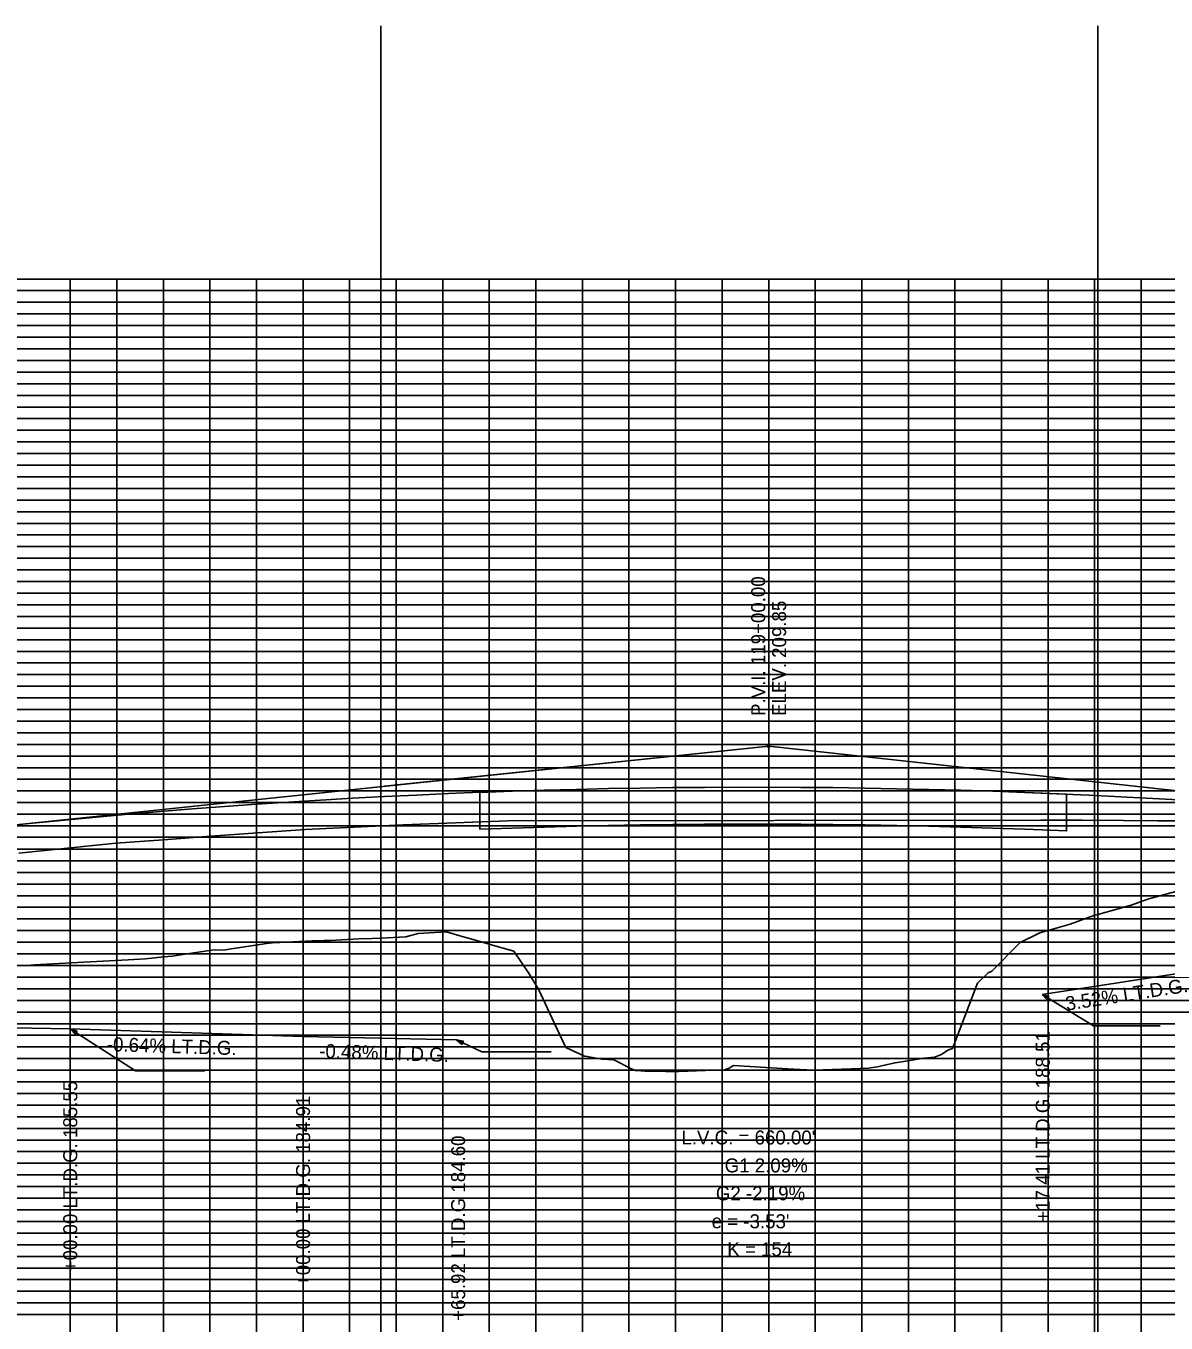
# Model space of a CAD drawing. Extents: x 1451449 to 1456010, y 297581 to 299758.
# Drawn here: x 1453061 to 1453550, y 299105 to 299662 of the extents above; entities that cross this region are included whole.
import ezdxf

# ---------------------------------------------------------------- set-up
doc = ezdxf.new("R2010")
doc.units = 0
for name, color, linetype in [('Existing Profile Grade', 7, 'Continuous'), ('Grid', 7, 'Continuous'), ('Grid_Major', 7, 'Continuous'), ('Grid_Minor', 7, 'Continuous'), ('PR_Exist Surface', 7, 'Continuous'), ('PR_exist_ground', 7, 'Continuous'), ('PR_PGL_point', 7, 'Continuous'), ('PRF_Bridge', 7, 'Continuous'), ('PRF_Scratch', 7, 'Continuous'), ('Profile Annotation', 7, 'Continuous'), ('Profile Annotation Line', 7, 'Continuous'), ('Special_Ditch_LT', 7, 'Continuous')]:
    doc.layers.add(name, color=color, linetype=linetype)

msp = doc.modelspace()

# ---------------------------------------------------------------- linework, layer by layer
at = {"layer": 'Existing Profile Grade'}
msp.add_line((1453496.53, 299321), (1453267.66, 299320.78), dxfattribs=at)
for points in [[(1453057.64, 299306.77), (1453078.47, 299308.95), (1453099.3, 299311.13), (1453119.66, 299312.62), (1453140.01, 299314.12), (1453160.31, 299315.58), (1453180.62, 299317.05), (1453201.65, 299318), (1453222.64, 299318.96), (1453245.15, 299319.87), (1453267.66, 299320.78)], [(1453496.53, 299321), (1453514.29, 299320.93), (1453532.09, 299320.86), (1453546.85, 299320.78), (1453561.6, 299320.71), (1453579.05, 299320.08), (1453596.5, 299319.44), (1453616.07, 299318.37), (1453635.64, 299317.31), (1453650.94, 299316.15)]]:
    msp.add_lwpolyline(points, dxfattribs=at)
at = {"layer": 'Grid'}
for p, q in [((1453213.11, 298828.55), (1453213.11, 299662.3)), ((1453521, 298828.55), (1453521, 299662.3))]:
    msp.add_line(p, q, dxfattribs=at)
at = {"layer": 'Grid_Major'}
for p, q in [((1451479.67, 299553.55), (1455979.67, 299553.55)), ((1451479.67, 299553.55), (1455979.67, 299553.55)), ((1453079.67, 298953.55), (1453079.67, 299553.55)), ((1453179.67, 298953.55), (1453179.67, 299553.55)), ((1453279.67, 298953.55), (1453279.67, 299553.55)), ((1453379.67, 298953.55), (1453379.67, 299553.55)), ((1453479.67, 298953.55), (1453479.67, 299553.55)), ((1451479.67, 299503.55), (1455979.67, 299503.55)), ((1451479.67, 299453.55), (1455979.67, 299453.55)), ((1451479.67, 299403.55), (1455979.67, 299403.55)), ((1451479.67, 299353.55), (1455979.67, 299353.55)), ((1451479.67, 299303.55), (1455979.67, 299303.55)), ((1451479.67, 299253.55), (1455979.67, 299253.55)), ((1451479.67, 299203.55), (1455979.67, 299203.55)), ((1451479.67, 299153.55), (1455979.67, 299153.55))]:
    msp.add_line(p, q, dxfattribs=at)
at = {"layer": 'Grid_Minor'}
for p, q in [((1453099.67, 298953.55), (1453099.67, 299553.55)), ((1453119.67, 298953.55), (1453119.67, 299553.55)), ((1453139.67, 298953.55), (1453139.67, 299553.55)), ((1453159.67, 298953.55), (1453159.67, 299553.55)), ((1453199.67, 298953.55), (1453199.67, 299553.55)), ((1453219.67, 298953.55), (1453219.67, 299553.55)), ((1453239.67, 298953.55), (1453239.67, 299553.55)), ((1453259.67, 298953.55), (1453259.67, 299553.55)), ((1453299.67, 298953.55), (1453299.67, 299553.55)), ((1453319.67, 298953.55), (1453319.67, 299553.55)), ((1453339.67, 298953.55), (1453339.67, 299553.55)), ((1453359.67, 298953.55), (1453359.67, 299553.55)), ((1453399.67, 298953.55), (1453399.67, 299553.55)), ((1453419.67, 298953.55), (1453419.67, 299553.55)), ((1453439.67, 298953.55), (1453439.67, 299553.55)), ((1453459.67, 298953.55), (1453459.67, 299553.55)), ((1453499.67, 298953.55), (1453499.67, 299553.55)), ((1453519.67, 298953.55), (1453519.67, 299553.55)), ((1453539.67, 298953.55), (1453539.67, 299553.55)), ((1451479.67, 299548.55), (1455979.67, 299548.55)), ((1451479.67, 299543.55), (1455979.67, 299543.55)), ((1451479.67, 299538.55), (1455979.67, 299538.55)), ((1451479.67, 299533.55), (1455979.67, 299533.55)), ((1451479.67, 299528.55), (1455979.67, 299528.55)), ((1451479.67, 299523.55), (1455979.67, 299523.55)), ((1451479.67, 299518.55), (1455979.67, 299518.55)), ((1451479.67, 299513.55), (1455979.67, 299513.55)), ((1451479.67, 299508.55), (1455979.67, 299508.55)), ((1451479.67, 299498.55), (1455979.67, 299498.55)), ((1451479.67, 299493.55), (1455979.67, 299493.55)), ((1451479.67, 299488.55), (1455979.67, 299488.55)), ((1451479.67, 299483.55), (1455979.67, 299483.55)), ((1451479.67, 299478.55), (1455979.67, 299478.55)), ((1451479.67, 299473.55), (1455979.67, 299473.55)), ((1451479.67, 299468.55), (1455979.67, 299468.55)), ((1451479.67, 299463.55), (1455979.67, 299463.55)), ((1451479.67, 299458.55), (1455979.67, 299458.55)), ((1451479.67, 299448.55), (1455979.67, 299448.55)), ((1451479.67, 299443.55), (1455979.67, 299443.55)), ((1451479.67, 299438.55), (1455979.67, 299438.55)), ((1451479.67, 299433.55), (1455979.67, 299433.55)), ((1451479.67, 299428.55), (1455979.67, 299428.55)), ((1451479.67, 299423.55), (1455979.67, 299423.55)), ((1451479.67, 299418.55), (1455979.67, 299418.55)), ((1451479.67, 299413.55), (1455979.67, 299413.55)), ((1451479.67, 299408.55), (1455979.67, 299408.55)), ((1451479.67, 299398.55), (1455979.67, 299398.55)), ((1451479.67, 299393.55), (1455979.67, 299393.55)), ((1451479.67, 299388.55), (1455979.67, 299388.55)), ((1451479.67, 299383.55), (1455979.67, 299383.55)), ((1451479.67, 299378.55), (1455979.67, 299378.55)), ((1451479.67, 299373.55), (1455979.67, 299373.55)), ((1451479.67, 299368.55), (1455979.67, 299368.55)), ((1451479.67, 299363.55), (1455979.67, 299363.55)), ((1451479.67, 299358.55), (1455979.67, 299358.55)), ((1451479.67, 299348.55), (1455979.67, 299348.55)), ((1451479.67, 299343.55), (1455979.67, 299343.55)), ((1451479.67, 299338.55), (1455979.67, 299338.55)), ((1451479.67, 299333.55), (1455979.67, 299333.55)), ((1451479.67, 299328.55), (1455979.67, 299328.55)), ((1451479.67, 299323.55), (1455979.67, 299323.55)), ((1451479.67, 299318.55), (1455979.67, 299318.55)), ((1451482.2, 299313.64), (1455982.2, 299313.64)), ((1451479.67, 299308.55), (1455979.67, 299308.55)), ((1451479.67, 299298.55), (1455979.67, 299298.55)), ((1451479.67, 299293.55), (1455979.67, 299293.55)), ((1451479.67, 299288.55), (1455979.67, 299288.55)), ((1451479.67, 299283.55), (1455979.67, 299283.55)), ((1451479.67, 299278.55), (1455979.67, 299278.55)), ((1451479.67, 299273.55), (1455979.67, 299273.55)), ((1451479.67, 299268.55), (1455979.67, 299268.55)), ((1451479.67, 299263.55), (1455979.67, 299263.55)), ((1451479.67, 299258.55), (1455979.67, 299258.55)), ((1451479.67, 299248.55), (1455979.67, 299248.55)), ((1451479.67, 299243.55), (1455979.67, 299243.55)), ((1451479.67, 299238.55), (1455979.67, 299238.55)), ((1451479.67, 299233.55), (1455979.67, 299233.55)), ((1451479.67, 299228.55), (1455979.67, 299228.55)), ((1451479.67, 299223.55), (1455979.67, 299223.55)), ((1451479.67, 299218.55), (1455979.67, 299218.55)), ((1451479.67, 299213.55), (1455979.67, 299213.55)), ((1451479.67, 299208.55), (1455979.67, 299208.55)), ((1451479.67, 299198.55), (1455979.67, 299198.55)), ((1451479.67, 299193.55), (1455979.67, 299193.55)), ((1451479.67, 299188.55), (1455979.67, 299188.55)), ((1451479.67, 299183.55), (1455979.67, 299183.55)), ((1451479.67, 299178.55), (1455979.67, 299178.55)), ((1451479.67, 299173.55), (1455979.67, 299173.55)), ((1451479.67, 299168.55), (1455979.67, 299168.55)), ((1451479.67, 299163.55), (1455979.67, 299163.55)), ((1451479.67, 299158.55), (1455979.67, 299158.55)), ((1451479.67, 299148.55), (1455979.67, 299148.55)), ((1451479.67, 299143.55), (1455979.67, 299143.55)), ((1451479.67, 299138.55), (1455979.67, 299138.55)), ((1451479.67, 299133.55), (1455979.67, 299133.55)), ((1451479.67, 299128.55), (1455979.67, 299128.55)), ((1451479.67, 299123.55), (1455979.67, 299123.55)), ((1451479.67, 299118.55), (1455979.67, 299118.55)), ((1451479.67, 299113.55), (1455979.67, 299113.55)), ((1451479.67, 299108.55), (1455979.67, 299108.55))]:
    msp.add_line(p, q, dxfattribs=at)
at = {"layer": 'PR_Exist Surface'}
msp.add_lwpolyline([(1453060, 299258.49), (1453061.09, 299258.58), (1453064.38, 299258.88), (1453082.8, 299259.84), (1453104.52, 299261.04), (1453111.93, 299261.48), (1453115.98, 299261.86), (1453119.88, 299262.23), (1453123.62, 299262.59), (1453126.24, 299262.98), (1453141.39, 299265.29), (1453145.64, 299265.19), (1453147.96, 299265.54), (1453164, 299267.99), (1453167.89, 299268.38), (1453169.68, 299268.46), (1453183.6, 299269.1), (1453188.57, 299269.24), (1453191.4, 299269.36), (1453203.62, 299269.95), (1453209.36, 299270.13), (1453213.11, 299270.31), (1453223.79, 299270.83), (1453229.11, 299272.26), (1453241.27, 299272.97), (1453247.01, 299271.25), (1453255.73, 299268.84), (1453261.07, 299267.24), (1453270.22, 299264.73), (1453276.82, 299255.02), (1453280.97, 299248.15), (1453287.6, 299233.92), (1453292.52, 299223.38), (1453300.5, 299219.59), (1453301.75, 299219.49), (1453308, 299218.34), (1453313.2, 299217.99), (1453321.06, 299214.02), (1453321.46, 299213.85), (1453322.04, 299213.56), (1453322.83, 299213.33), (1453322.86, 299213.42), (1453326.6, 299213.14), (1453335.46, 299213.01), (1453341.09, 299212.96), (1453352.57, 299213.38), (1453360.67, 299213.65), (1453362.68, 299214.47), (1453364.53, 299215.63), (1453387.77, 299214.17), (1453398.72, 299213.53), (1453415.28, 299214.2), (1453422.66, 299214.44), (1453424.35, 299214.71), (1453426.39, 299215.04), (1453427.59, 299215.3), (1453429.48, 299215.71), (1453433.96, 299216.73), (1453437.71, 299217.35), (1453444.57, 299218.43), (1453446.34, 299218.77), (1453450.92, 299219.13), (1453453.87, 299220.36), (1453456.16, 299221.84), (1453457.32, 299222.45), (1453458.61, 299222.85), (1453460.06, 299226.66), (1453469.36, 299250.95), (1453474.02, 299255.39), (1453475.58, 299256.08), (1453487.67, 299268.37), (1453496.2, 299272.53), (1453509.12, 299276.3), (1453519.36, 299279.99), (1453521, 299280.45), (1453535.38, 299284.5), (1453542.5, 299287.03), (1453543.02, 299287.17), (1453562.38, 299292.43)], dxfattribs=at)
at = {"layer": 'PR_exist_ground'}
for p, q in [((1453522.25, 299232.68), (1453547.81, 299232.68)), ((1453259.47, 299221.42), (1453286.24, 299221.42)), ((1453110.73, 299213.35), (1453137.48, 299213.35))]:
    msp.add_line(p, q, dxfattribs=at)
for points in [[(1453049.67, 299318.31), (1453063.42, 299319.72), (1453077.17, 299321.06), (1453090.92, 299322.34), (1453104.67, 299323.57), (1453118.42, 299324.73), (1453132.17, 299325.83), (1453145.92, 299326.87), (1453159.67, 299327.84), (1453173.42, 299328.76), (1453187.17, 299329.62), (1453200.92, 299330.41), (1453214.67, 299331.14), (1453228.42, 299331.81), (1453242.17, 299332.42), (1453255.92, 299332.97), (1453269.67, 299333.46), (1453283.42, 299333.89), (1453297.17, 299334.25), (1453310.92, 299334.55), (1453324.67, 299334.8), (1453338.42, 299334.98), (1453352.17, 299335.1), (1453365.92, 299335.16), (1453393.42, 299335.09), (1453407.17, 299334.97), (1453420.92, 299334.78), (1453434.67, 299334.53), (1453448.42, 299334.22), (1453462.17, 299333.85), (1453475.92, 299333.42), (1453489.67, 299332.93), (1453503.42, 299332.38), (1453517.17, 299331.76), (1453530.92, 299331.08), (1453544.67, 299330.35), (1453558.42, 299329.55)], [(1453049.67, 299318.31), (1453063.42, 299319.72), (1453077.17, 299321.06), (1453090.92, 299322.34), (1453104.67, 299323.57), (1453118.42, 299324.73), (1453132.17, 299325.83), (1453145.92, 299326.87), (1453159.67, 299327.84), (1453173.42, 299328.76), (1453187.17, 299329.62), (1453200.92, 299330.41), (1453214.67, 299331.14), (1453228.42, 299331.81), (1453242.17, 299332.42), (1453255.92, 299332.97), (1453269.67, 299333.46), (1453283.42, 299333.89), (1453297.17, 299334.25), (1453310.92, 299334.55), (1453324.67, 299334.8), (1453338.42, 299334.98), (1453352.17, 299335.1), (1453365.92, 299335.16), (1453393.42, 299335.09), (1453407.17, 299334.97), (1453420.92, 299334.78), (1453434.67, 299334.53), (1453448.42, 299334.22), (1453462.17, 299333.85), (1453475.92, 299333.42), (1453489.67, 299332.93), (1453503.42, 299332.38), (1453517.17, 299331.76), (1453530.92, 299331.08), (1453544.67, 299330.35), (1453558.42, 299329.55)], [(1453049.67, 299318.31), (1453063.42, 299319.72), (1453077.17, 299321.06), (1453090.92, 299322.34), (1453104.67, 299323.57), (1453118.42, 299324.73), (1453132.17, 299325.83), (1453145.92, 299326.87), (1453159.67, 299327.84), (1453173.42, 299328.76), (1453187.17, 299329.62), (1453200.92, 299330.41), (1453214.67, 299331.14), (1453228.42, 299331.81), (1453242.17, 299332.42), (1453255.92, 299332.97), (1453269.67, 299333.46), (1453283.42, 299333.89), (1453297.17, 299334.25), (1453310.92, 299334.55), (1453324.67, 299334.8), (1453338.42, 299334.98), (1453352.17, 299335.1), (1453365.92, 299335.16), (1453393.42, 299335.09), (1453407.17, 299334.97), (1453420.92, 299334.78), (1453434.67, 299334.53), (1453448.42, 299334.22), (1453462.17, 299333.85), (1453475.92, 299333.42), (1453489.67, 299332.93), (1453503.42, 299332.38), (1453517.17, 299331.76), (1453530.92, 299331.08), (1453544.67, 299330.35), (1453558.42, 299329.55)], [(1453049.67, 299318.31), (1453063.42, 299319.72), (1453077.17, 299321.06), (1453090.92, 299322.34), (1453104.67, 299323.57), (1453118.42, 299324.73), (1453132.17, 299325.83), (1453145.92, 299326.87), (1453159.67, 299327.84), (1453173.42, 299328.76), (1453187.17, 299329.62), (1453200.92, 299330.41), (1453214.67, 299331.14), (1453228.42, 299331.81), (1453242.17, 299332.42), (1453255.92, 299332.97), (1453269.67, 299333.46), (1453283.42, 299333.89), (1453297.17, 299334.25), (1453310.92, 299334.55), (1453324.67, 299334.8), (1453338.42, 299334.98), (1453352.17, 299335.1), (1453365.92, 299335.16), (1453393.42, 299335.09), (1453407.17, 299334.97), (1453420.92, 299334.78), (1453434.67, 299334.53), (1453448.42, 299334.22), (1453462.17, 299333.85), (1453475.92, 299333.42), (1453489.67, 299332.93), (1453503.42, 299332.38), (1453517.17, 299331.76), (1453530.92, 299331.08), (1453544.67, 299330.35), (1453558.42, 299329.55)], [(1453049.67, 299318.31), (1453063.42, 299319.72), (1453077.17, 299321.06), (1453090.92, 299322.34), (1453104.67, 299323.57), (1453118.42, 299324.73), (1453132.17, 299325.83), (1453145.92, 299326.87), (1453159.67, 299327.84), (1453173.42, 299328.76), (1453187.17, 299329.62), (1453200.92, 299330.41), (1453214.67, 299331.14), (1453228.42, 299331.81), (1453242.17, 299332.42), (1453255.92, 299332.97), (1453269.67, 299333.46), (1453283.42, 299333.89), (1453297.17, 299334.25), (1453310.92, 299334.55), (1453324.67, 299334.8), (1453338.42, 299334.98), (1453352.17, 299335.1), (1453365.92, 299335.16), (1453393.42, 299335.09), (1453407.17, 299334.97), (1453420.92, 299334.78), (1453434.67, 299334.53), (1453448.42, 299334.22), (1453462.17, 299333.85), (1453475.92, 299333.42), (1453489.67, 299332.93), (1453503.42, 299332.38), (1453517.17, 299331.76), (1453530.92, 299331.08), (1453544.67, 299330.35), (1453558.42, 299329.55)], [(1453497.08, 299246.1), (1453519.25, 299232.68), (1453522.25, 299232.68)], [(1453079.67, 299231.3), (1453107.73, 299213.35), (1453110.73, 299213.35)], [(1453245.59, 299226.55), (1453256.47, 299221.42), (1453259.47, 299221.42)]]:
    msp.add_lwpolyline(points, dxfattribs=at)
for points in [[(1453497.08, 299246.1), (1453499.94, 299245.21), (1453499.19, 299243.97)], [(1453079.67, 299231.3), (1453082.51, 299230.34), (1453081.73, 299229.11)], [(1453245.59, 299226.55), (1453248.53, 299225.96), (1453247.91, 299224.65)]]:
    msp.add_lwpolyline(points, close=True, dxfattribs=at)
at = {"layer": 'PR_PGL_point'}
msp.add_circle((1453379.67, 299352.79), 0.5, dxfattribs=at)
msp.add_circle((1453379.67, 299352.79), 0.5, dxfattribs=at)
msp.add_circle((1453379.67, 299352.79), 0.5, dxfattribs=at)
msp.add_circle((1453379.67, 299352.79), 0.5, dxfattribs=at)
msp.add_circle((1453379.67, 299352.79), 0.5, dxfattribs=at)
msp.add_circle((1453379.67, 299352.79), 0.5, dxfattribs=at)
msp.add_circle((1453379.67, 299352.79), 0.5, dxfattribs=at)
msp.add_circle((1453379.67, 299352.79), 0.5, dxfattribs=at)
msp.add_circle((1453379.67, 299352.79), 0.5, dxfattribs=at)
msp.add_circle((1453379.67, 299352.79), 0.5, dxfattribs=at)
at = {"layer": 'PRF_Bridge'}
for p, q in [((1453255.67, 299317.13), (1453255.67, 299332.96)), ((1453497.08, 299332.63), (1453489.67, 299332.93)), ((1453507.67, 299316.35), (1453507.67, 299332.19))]:
    msp.add_line(p, q, dxfattribs=at)
for points in [[(1453489.67, 299332.93), (1453475.92, 299333.42), (1453462.17, 299333.85), (1453448.42, 299334.22), (1453434.67, 299334.53), (1453420.92, 299334.78), (1453407.17, 299334.97), (1453393.42, 299335.09), (1453365.92, 299335.16), (1453352.17, 299335.1), (1453338.42, 299334.98), (1453324.67, 299334.8), (1453310.92, 299334.55), (1453297.17, 299334.25), (1453283.42, 299333.89), (1453269.67, 299333.46), (1453255.67, 299332.96)], [(1453255.67, 299332.96), (1453255.67, 299317.13)], [(1453497.08, 299316.8), (1453507.67, 299316.35), (1453507.67, 299332.19), (1453497.08, 299332.63)], [(1453255.67, 299317.13), (1453269.67, 299317.63), (1453283.42, 299318.05), (1453297.17, 299318.42), (1453310.92, 299318.72), (1453324.67, 299318.96), (1453338.42, 299319.14), (1453352.17, 299319.26), (1453365.92, 299319.32), (1453393.42, 299319.26), (1453407.17, 299319.13), (1453420.92, 299318.95), (1453434.67, 299318.7), (1453448.42, 299318.39), (1453462.17, 299318.02), (1453475.92, 299317.59), (1453489.67, 299317.1), (1453497.08, 299316.8)]]:
    msp.add_lwpolyline(points, dxfattribs=at)
at = {"layer": 'PRF_Scratch'}
for p, q in [((1453379.67, 299352.79), (1453379.67, 299454.79)), ((1452577.64, 299268.98), (1453379.67, 299352.79)), ((1452577.64, 299268.98), (1453379.67, 299352.79)), ((1452577.64, 299268.98), (1453379.67, 299352.79)), ((1452577.64, 299268.98), (1453379.67, 299352.79)), ((1452577.64, 299268.98), (1453379.67, 299352.79)), ((1452577.64, 299268.98), (1453379.67, 299352.79)), ((1452727.64, 299284.66), (1453379.67, 299352.79)), ((1453214.67, 299335.55), (1453379.67, 299352.79)), ((1453379.67, 299352.79), (1453983.52, 299286.78)), ((1453379.67, 299352.79), (1453983.52, 299286.78)), ((1453379.67, 299352.79), (1453983.52, 299286.78)), ((1453379.67, 299352.79), (1453983.52, 299286.78)), ((1453379.67, 299352.79), (1453983.52, 299286.78)), ((1453379.67, 299352.79), (1453983.52, 299286.78)), ((1453379.67, 299352.79), (1453544.67, 299334.76))]:
    msp.add_line(p, q, dxfattribs=at)
msp.add_lwpolyline([(1453049.67, 299318.31), (1453063.42, 299319.72), (1453077.17, 299321.06), (1453090.92, 299322.34), (1453104.67, 299323.57), (1453118.42, 299324.73), (1453132.17, 299325.83), (1453145.92, 299326.87), (1453159.67, 299327.84), (1453173.42, 299328.76), (1453187.17, 299329.62), (1453200.92, 299330.41), (1453214.67, 299331.14), (1453228.42, 299331.81), (1453242.17, 299332.42), (1453255.92, 299332.97), (1453269.67, 299333.46), (1453283.42, 299333.89), (1453297.17, 299334.25), (1453310.92, 299334.55), (1453324.67, 299334.8), (1453338.42, 299334.98), (1453352.17, 299335.1), (1453365.92, 299335.16), (1453393.42, 299335.09), (1453407.17, 299334.97), (1453420.92, 299334.78), (1453434.67, 299334.53), (1453448.42, 299334.22), (1453462.17, 299333.85), (1453475.92, 299333.42), (1453489.67, 299332.93), (1453503.42, 299332.38), (1453517.17, 299331.76), (1453530.92, 299331.08), (1453544.67, 299330.35), (1453558.42, 299329.55)], dxfattribs=at)
msp.add_lwpolyline([(1453049.67, 299318.31), (1453063.42, 299319.72), (1453077.17, 299321.06), (1453090.92, 299322.34), (1453104.67, 299323.57), (1453118.42, 299324.73), (1453132.17, 299325.83), (1453145.92, 299326.87), (1453159.67, 299327.84), (1453173.42, 299328.76), (1453187.17, 299329.62), (1453200.92, 299330.41), (1453214.67, 299331.14), (1453228.42, 299331.81), (1453242.17, 299332.42), (1453255.92, 299332.97), (1453269.67, 299333.46), (1453283.42, 299333.89), (1453297.17, 299334.25), (1453310.92, 299334.55), (1453324.67, 299334.8), (1453338.42, 299334.98), (1453352.17, 299335.1), (1453365.92, 299335.16), (1453393.42, 299335.09), (1453407.17, 299334.97), (1453420.92, 299334.78), (1453434.67, 299334.53), (1453448.42, 299334.22), (1453462.17, 299333.85), (1453475.92, 299333.42), (1453489.67, 299332.93), (1453503.42, 299332.38), (1453517.17, 299331.76), (1453530.92, 299331.08), (1453544.67, 299330.35), (1453558.42, 299329.55)], dxfattribs=at)
msp.add_lwpolyline([(1453049.67, 299318.31), (1453063.42, 299319.72), (1453077.17, 299321.06), (1453090.92, 299322.34), (1453104.67, 299323.57), (1453118.42, 299324.73), (1453132.17, 299325.83), (1453145.92, 299326.87), (1453159.67, 299327.84), (1453173.42, 299328.76), (1453187.17, 299329.62), (1453200.92, 299330.41), (1453214.67, 299331.14), (1453228.42, 299331.81), (1453242.17, 299332.42), (1453255.92, 299332.97), (1453269.67, 299333.46), (1453283.42, 299333.89), (1453297.17, 299334.25), (1453310.92, 299334.55), (1453324.67, 299334.8), (1453338.42, 299334.98), (1453352.17, 299335.1), (1453365.92, 299335.16), (1453393.42, 299335.09), (1453407.17, 299334.97), (1453420.92, 299334.78), (1453434.67, 299334.53), (1453448.42, 299334.22), (1453462.17, 299333.85), (1453475.92, 299333.42), (1453489.67, 299332.93), (1453503.42, 299332.38), (1453517.17, 299331.76), (1453530.92, 299331.08), (1453544.67, 299330.35), (1453558.42, 299329.55)], dxfattribs=at)
msp.add_circle((1453379.67, 299352.79), 0.5, dxfattribs=at)
at = {"layer": 'Profile Annotation Line'}
for p, q in [((1453379.67, 299352.79), (1453379.67, 299454.79)), ((1453214.67, 299335.55), (1453379.67, 299352.79)), ((1453379.67, 299352.79), (1453544.67, 299334.76))]:
    msp.add_line(p, q, dxfattribs=at)
at = {"layer": 'Special_Ditch_LT'}
for points in [[(1453497.08, 299246.1), (1453579.67, 299258.9), (1453679.67, 299259.9)], [(1452379.67, 299242.2), (1452479.67, 299241.65), (1452579.67, 299239.92), (1452679.67, 299238.2), (1452779.67, 299236.47), (1452797.41, 299236.16), (1452879.67, 299234.75), (1452979.67, 299233.02), (1453079.67, 299231.3), (1453179.67, 299228.1), (1453245.59, 299226.55)]]:
    msp.add_lwpolyline(points, dxfattribs=at)

# ---------------------------------------------------------------- texts
at = {"layer": 'PRF_Scratch'}
for s, p in [('P.V.I. 119+00.00', (1453378.17, 299365.79)), ('ELEV. 209.85', (1453387.17, 299365.79))]:
    msp.add_text(s, height=6, rotation=90, dxfattribs=at).set_placement(p)
at = {"layer": 'Profile Annotation'}
for s, rotation, p in [('P.V.I. 119+00.00', 90, (1453378.17, 299365.79)), ('ELEV. 209.85', 90, (1453387.17, 299365.79)), ('3.52% LT.D.G.', 8.8098, (1453507.64, 299239.12)), ('+17.41 LT.D.G. 188.51', 90, (1453500.38, 299148.47)), ('-0.64% LT.D.G.', 358.1672, (1453095.31, 299221.8)), ('-0.48% LT.D.G.', 358.1672, (1453186.52, 299218.87)), ('+00.00 LT.D.G. 185.55', 90, (1453082.67, 299127.13)), ('+00.00 LT.D.G. 184.91', 90, (1453182.67, 299120.75)), ('+65.92 LT.D.G 184.60', 90, (1453249.3, 299105.85))]:
    msp.add_text(s, height=6, rotation=rotation, dxfattribs=at).set_placement(p)
for s, p in [("L.V.C. = 660.00'", (1453342.19, 299181.63)), ('G1 2.09%', (1453360.77, 299169.63)), ('G2 -2.19%', (1453356.99, 299157.63)), ("e = -3.53'", (1453355.18, 299145.63)), ('K = 154', (1453361.9, 299133.63))]:
    msp.add_text(s, height=6, dxfattribs=at).set_placement(p)

doc.saveas('drawing.dxf')
